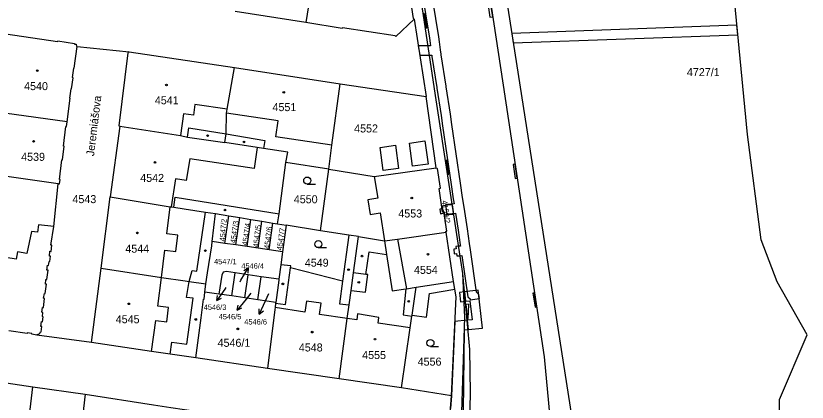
# Model space of a CAD drawing. Extents: x -756746 to -753363, y -1166406 to -1161727.
# Drawn here: x -754988.8 to -754820.8, y -1165946.8 to -1165864.8 of the extents above; entities that cross this region are included whole.
import ezdxf

# ---------------------------------------------------------------- set-up
doc = ezdxf.new("R2010")
doc.units = 0
for name, color, linetype in [('Hranice kat_území', 7, 'Continuous'), ('Hranice parcel', 7, 'Continuous'), ('Parcelní čísla', 7, 'Continuous'), ('Pop  PČ popisy', 7, 'Continuous'), ('Vnitřní kresba', 7, 'Continuous'), ('Věcná břemena k části', 7, 'Continuous'), ('Značky budov', 7, 'Continuous'), ('Značky kultur', 7, 'Continuous')]:
    doc.layers.add(name, color=color, linetype=linetype)

msp = doc.modelspace()

# ---------------------------------------------------------------- linework, layer by layer
at = {"layer": 'Hranice kat_území'}
msp.add_lwpolyline([(-754827.13, -1165983.58), (-754826.69, -1165946.26), (-754820.79, -1165932.53), (-754827.17, -1165921.24), (-754830.58, -1165912.37), (-754833.44, -1165889.97), (-754837.95, -1165843.7)], dxfattribs=at)
at = {"layer": 'Hranice parcel'}
for p, q in [((-754927.22, -1165866.24), (-754942.23, -1165863.89)), ((-754904.23, -1165865.47), (-754901.67, -1165881.94)), ((-754975.76, -1165871.3), (-754964.74, -1165872.4)), ((-754964.74, -1165872.4), (-754942.38, -1165875.74)), ((-754942.38, -1165875.74), (-754919.95, -1165879.22)), ((-754919.95, -1165879.22), (-754901.67, -1165881.94)), ((-754899.53, -1165897.07), (-754901.67, -1165881.94)), ((-754966.7, -1165888.2), (-754968.78, -1165903.24)), ((-754922.31, -1165897.32), (-754931.46, -1165895.91)), ((-754924.11, -1165910.4), (-754922.31, -1165897.32)), ((-754970.69, -1165918.35), (-754968.78, -1165903.24)), ((-754947.08, -1165912.68), (-754946.39, -1165906.78)), ((-754946.39, -1165906.78), (-754943.58, -1165907.24)), ((-754944.4, -1165913.09), (-754943.58, -1165907.24)), ((-754943.58, -1165907.24), (-754941.25, -1165907.63)), ((-754942.06, -1165913.43), (-754941.25, -1165907.63)), ((-754941.25, -1165907.63), (-754938.91, -1165908.01)), ((-754939.7, -1165913.77), (-754938.91, -1165908.01)), ((-754938.91, -1165908.01), (-754936.56, -1165908.4)), ((-754937.34, -1165914.11), (-754936.56, -1165908.4)), ((-754936.56, -1165908.4), (-754934.2, -1165908.79)), ((-754934.98, -1165914.46), (-754934.2, -1165908.79)), ((-754934.2, -1165908.79), (-754933.2, -1165908.95)), ((-754933.2, -1165908.95), (-754931.37, -1165909.24)), ((-754931.37, -1165909.24), (-754932.14, -1165914.86)), ((-754924.11, -1165910.4), (-754931.37, -1165909.24)), ((-754918.12, -1165911.32), (-754924.11, -1165910.4)), ((-754895.85, -1165921.16), (-754897.45, -1165910.69)), ((-754944.4, -1165913.09), (-754947.08, -1165912.68)), ((-754916.04, -1165911.63), (-754918.12, -1165911.32)), ((-754916.04, -1165911.63), (-754910.55, -1165912.57)), ((-754942.06, -1165913.43), (-754944.4, -1165913.09)), ((-754939.7, -1165913.77), (-754942.06, -1165913.43)), ((-754937.34, -1165914.11), (-754939.7, -1165913.77)), ((-754934.98, -1165914.46), (-754937.34, -1165914.11)), ((-754932.14, -1165914.86), (-754934.98, -1165914.46)), ((-754932.14, -1165914.86), (-754932.53, -1165917.68)), ((-754932.53, -1165917.68), (-754932.92, -1165920.68)), ((-754972.7, -1165934.17), (-754970.69, -1165918.35)), ((-754942.92, -1165924.26), (-754942.24, -1165919.37)), ((-754939.45, -1165919.8), (-754942.24, -1165919.37)), ((-754940.17, -1165924.66), (-754939.45, -1165919.8)), ((-754936.69, -1165920.2), (-754939.45, -1165919.8)), ((-754937.38, -1165925.07), (-754936.69, -1165920.2)), ((-754932.92, -1165920.68), (-754936.69, -1165920.2)), ((-754948.63, -1165923.42), (-754948.41, -1165921.7)), ((-754903.78, -1165922.39), (-754895.85, -1165921.16)), ((-754945.66, -1165923.85), (-754948.63, -1165923.42)), ((-754942.92, -1165924.26), (-754945.66, -1165923.85)), ((-754940.17, -1165924.66), (-754942.92, -1165924.26)), ((-754937.38, -1165925.07), (-754940.17, -1165924.66)), ((-754933.6, -1165925.62), (-754937.38, -1165925.07)), ((-754984.31, -1165932.57), (-754984.29, -1165932.43)), ((-754972.7, -1165934.17), (-754984.31, -1165932.57)), ((-754826.69, -1165946.26), (-754820.79, -1165932.53)), ((-754935.37, -1165939.67), (-754950.56, -1165937.42)), ((-754920.11, -1165941.86), (-754935.37, -1165939.67)), ((-754906.91, -1165943.78), (-754920.11, -1165941.86)), ((-754987.57, -1165962.84), (-754985.14, -1165943.54)), ((-754985.14, -1165943.54), (-754974.08, -1165945.13)), ((-754896.29, -1165945.45), (-754906.91, -1165943.78)), ((-754827.13, -1165983.58), (-754826.69, -1165946.26))]:
    msp.add_line(p, q, dxfattribs=at)
for points in [[(-754893.87, -1165919.46), (-754899.67, -1165881.69), (-754902.28, -1165864.2), (-754904.91, -1165847.27), (-754914.1, -1165786.01), (-754916.16, -1165772.03), (-754920.31, -1165744.22), (-754925.86, -1165707.53), (-754934.37, -1165652.04), (-754940.69, -1165610.27), (-754945.47, -1165583.65), (-754957.29, -1165524.97), (-754963.86, -1165505.86), (-754970.07, -1165475.28), (-754974.11, -1165441.89), (-754977.86, -1165423.12), (-754982.77, -1165403.72), (-754984.71, -1165394.8), (-754990.28, -1165381.95), (-754996.53, -1165351.07), (-755004.37, -1165309.56), (-755007.34, -1165270.19), (-755010.72, -1165249.36), (-755016.18, -1165250.63)], [(-754986.88, -1165279.38), (-754990.41, -1165279.86), (-754980.99, -1165331.36), (-754966.52, -1165403.04), (-754962.21, -1165426.7), (-754948.35, -1165495.48), (-754937.5, -1165549.21), (-754928.46, -1165594.05), (-754928.31, -1165595.05), (-754927.98, -1165597.22), (-754926.04, -1165609.85), (-754919.91, -1165650.59), (-754911.7, -1165704.69), (-754902.24, -1165767.33), (-754892.9, -1165829.68), (-754885.35, -1165879.53), (-754876.62, -1165937.17), (-754872.47, -1165981.85), (-754871.4, -1165985.78), (-754868.4, -1165989.67), (-754864.36, -1165991.91), (-754859.05, -1165992.04), (-754854.87, -1165991.29)], [(-754923.98, -1165615.89), (-754912.58, -1165682.53), (-754887.89, -1165840.42), (-754864.72, -1165988.62), (-754860.06, -1165990.02), (-754855.25, -1165989.37)], [(-754833.44, -1165889.97), (-754837.95, -1165843.7), (-754842.97, -1165786.69), (-754844.24, -1165752.2), (-754845.04, -1165691.76), (-754839.18, -1165652.65)], [(-754904.23, -1165865.47), (-754904.34, -1165865.36), (-754906.43, -1165851.68), (-754906.27, -1165851.66), (-754907.29, -1165846.39)], [(-754924.25, -1165847.28), (-754925.14, -1165852.98), (-754925.48, -1165855.12), (-754927.22, -1165866.24)], [(-754904.23, -1165865.47), (-754908.11, -1165869.2), (-754908.24, -1165869.07), (-754919.46, -1165867.31), (-754919.48, -1165867.45), (-754927.22, -1165866.24)], [(-754996.6, -1165867.79), (-754996.58, -1165867.59), (-754995.76, -1165867.71), (-754995.79, -1165867.9), (-754993.52, -1165868.25), (-754993.49, -1165868.05), (-754992.86, -1165868.15), (-754992.88, -1165868.3), (-754979.91, -1165870.24), (-754979.89, -1165870.09), (-754976.29, -1165870.64), (-754976.31, -1165870.8), (-754975.99, -1165870.84), (-754975.88, -1165871.28), (-754975.76, -1165871.3)], [(-754977.88, -1165887.32), (-754977.22, -1165882.29), (-754977.35, -1165882.27), (-754977.06, -1165880.26), (-754976.95, -1165880.28), (-754976.64, -1165877.92), (-754976.74, -1165877.91), (-754976.5, -1165875.92), (-754976.38, -1165875.93), (-754975.76, -1165871.3)], [(-754964.74, -1165872.4), (-754965.01, -1165872.63), (-754966.89, -1165888.17), (-754966.7, -1165888.2)], [(-754944.43, -1165891.7), (-754944.11, -1165889.85), (-754944.04, -1165885.45), (-754943.89, -1165884.59), (-754942.38, -1165875.74)], [(-754922.31, -1165897.32), (-754921.72, -1165892.27), (-754919.95, -1165879.22)], [(-754977.88, -1165887.32), (-754991.18, -1165885.43), (-754998.96, -1165884.18)], [(-754979.76, -1165900.42), (-754979.52, -1165900.45), (-754979.4, -1165899.51), (-754979.52, -1165899.5), (-754979, -1165895.33), (-754978.88, -1165895.35), (-754978.53, -1165892.48), (-754978.64, -1165892.46), (-754978.13, -1165888.3), (-754978.01, -1165888.31), (-754977.88, -1165887.32)], [(-754966.7, -1165888.2), (-754953.85, -1165890.21), (-754952.34, -1165890.53), (-754944.43, -1165891.7)], [(-754820.79, -1165932.53), (-754827.17, -1165921.24), (-754830.58, -1165912.37), (-754833.44, -1165889.97)], [(-754931.46, -1165895.91), (-754931.05, -1165893.7), (-754936.19, -1165892.93), (-754937.53, -1165892.73), (-754944.43, -1165891.7)], [(-754933.2, -1165908.95), (-754932.89, -1165906.8), (-754931.46, -1165895.91)], [(-754979.76, -1165900.42), (-754992.77, -1165898.65), (-755000.73, -1165897.43)], [(-754922.31, -1165897.32), (-754912.69, -1165898.87), (-754899.53, -1165897.07)], [(-754897.45, -1165910.69), (-754897.48, -1165910.5), (-754897.27, -1165910.47), (-754897.9, -1165906.33), (-754898.18, -1165906.37), (-754898.92, -1165901.43), (-754898.65, -1165901.39), (-754899.3, -1165897.22), (-754899.5, -1165897.25), (-754899.53, -1165897.07)], [(-754983.53, -1165931.87), (-754983.4, -1165931.88), (-754983.26, -1165930.76), (-754983.48, -1165930.74), (-754983.35, -1165929.71), (-754983.13, -1165929.74), (-754983, -1165928.66), (-754983.15, -1165928.65), (-754983.04, -1165927.75), (-754983.24, -1165927.73), (-754983.11, -1165926.72), (-754982.91, -1165926.74), (-754982.67, -1165924.78), (-754982.88, -1165924.75), (-754982.69, -1165923.73), (-754982.55, -1165923.75), (-754982.3, -1165921.76), (-754982.5, -1165921.74), (-754982.4, -1165920.74), (-754982.18, -1165920.77), (-754981.93, -1165918.78), (-754982.17, -1165918.75), (-754982.05, -1165917.75), (-754981.81, -1165917.78), (-754981.67, -1165916.94), (-754981.55, -1165916.95), (-754981.42, -1165915.84), (-754981.66, -1165915.81), (-754981.53, -1165914.78), (-754981.29, -1165914.81), (-754981.13, -1165913.48), (-754981.35, -1165913.45), (-754980.71, -1165909.49), (-754979.76, -1165900.42)], [(-754968.78, -1165903.24), (-754955.99, -1165905.31), (-754955.83, -1165905.34), (-754955.27, -1165905.43), (-754953.03, -1165905.79), (-754948.55, -1165906.46), (-754946.39, -1165906.78)], [(-754910.55, -1165912.57), (-754907.74, -1165912.17), (-754897.45, -1165910.69)], [(-754948.41, -1165921.7), (-754948.08, -1165919.32), (-754947.19, -1165913.6), (-754947.08, -1165912.68)], [(-754918.12, -1165911.32), (-754919.45, -1165921.09), (-754930.46, -1165918.27), (-754930.41, -1165917.85), (-754932.53, -1165917.68)], [(-754920.11, -1165941.86), (-754918.41, -1165929.05), (-754918.03, -1165926.17), (-754917.61, -1165923.07), (-754917.12, -1165919.34), (-754916.04, -1165911.63)], [(-754910.55, -1165912.57), (-754910.1, -1165915.45), (-754908.89, -1165923.18), (-754906.01, -1165922.74), (-754905.86, -1165922.72), (-754903.78, -1165922.39)], [(-754970.69, -1165918.35), (-754957.84, -1165920.32), (-754952.85, -1165921.08), (-754952.01, -1165921.21), (-754948.41, -1165921.7)], [(-754942.24, -1165919.37), (-754944.04, -1165919.09), (-754944.73, -1165919.23), (-754945.07, -1165919.84), (-754945.66, -1165923.85)], [(-754899.06, -1165997.62), (-754897.71, -1165996.12), (-754896.74, -1165994.68), (-754896.09, -1165993.18), (-754895.65, -1165991.02), (-754895.42, -1165989.19), (-754895.29, -1165985.92), (-754895.17, -1165981), (-754894.31, -1165955.68), (-754893.44, -1165928.76), (-754893.87, -1165919.46)], [(-754893.38, -1165996.51), (-754893.19, -1165986.65), (-754892.29, -1165944.8), (-754892.4, -1165935.64), (-754893.87, -1165919.46)], [(-754932.92, -1165920.68), (-754932.95, -1165920.88), (-754933.6, -1165925.62)], [(-754906.91, -1165943.78), (-754905.07, -1165931), (-754904.7, -1165928.56), (-754904.66, -1165928.31), (-754903.78, -1165922.39)], [(-754896.29, -1165945.45), (-754895.33, -1165924.44), (-754895.59, -1165922.84), (-754895.85, -1165921.16)], [(-754950.56, -1165937.42), (-754949.42, -1165928.88), (-754948.96, -1165924.95), (-754948.83, -1165924.96), (-754948.63, -1165923.42)], [(-754933.6, -1165925.62), (-754933.63, -1165925.82), (-754933.74, -1165926.72), (-754933.79, -1165927.14), (-754935.37, -1165939.67)], [(-754984.31, -1165932.57), (-754985.4, -1165932.4), (-754985.36, -1165932.2), (-754986.35, -1165932.05), (-754986.38, -1165932.25), (-754990.25, -1165931.66)], [(-754984.29, -1165932.43), (-754984.02, -1165932.4), (-754983.83, -1165932.31), (-754983.64, -1165932.12), (-754983.53, -1165931.87)], [(-754950.56, -1165937.42), (-754955.99, -1165936.62), (-754959.95, -1165936.04), (-754972.7, -1165934.17)], [(-755005.55, -1165940.46), (-755000.89, -1165941.34), (-754997.77, -1165941.83), (-754996.1, -1165941.89), (-754985.14, -1165943.54)], [(-754974.08, -1165945.13), (-754974.93, -1165952.42), (-754975.07, -1165953.62), (-754975.38, -1165956.27), (-754975.65, -1165958.56)], [(-754974.08, -1165945.13), (-754959.58, -1165947.35), (-754955.85, -1165947.91), (-754947.14, -1165949.23), (-754944.47, -1165949.64)], [(-754904.83, -1165955.7), (-754897.71, -1165956.76), (-754897.12, -1165957.25), (-754896.9, -1165954.25), (-754896.53, -1165948.14), (-754896.29, -1165945.45)]]:
    msp.add_lwpolyline(points, dxfattribs=at)
at = {"layer": 'Pop  PČ popisy'}
for p, q in [((-754940.99, -1165920.9), (-754939.44, -1165918.33)), ((-754939.44, -1165918.33), (-754940.39, -1165918.93)), ((-754939.44, -1165918.33), (-754939.53, -1165919.44)), ((-754941.19, -1165921.24), (-754940.99, -1165920.9)), ((-754944.4, -1165922.79), (-754946.12, -1165925.25)), ((-754944.18, -1165922.47), (-754944.4, -1165922.79)), ((-754946.12, -1165925.25), (-754945.96, -1165924.14)), ((-754938.88, -1165923.68), (-754939.91, -1165924.94)), ((-754935.17, -1165923.82), (-754935.87, -1165925.35)), ((-754946.12, -1165925.25), (-754945.14, -1165924.72)), ((-754939.91, -1165924.94), (-754941.8, -1165927.27)), ((-754941.8, -1165927.27), (-754941.56, -1165926.18)), ((-754935.87, -1165925.35), (-754937.09, -1165928.09)), ((-754941.8, -1165927.27), (-754940.78, -1165926.81)), ((-754937.09, -1165928.09), (-754937.14, -1165926.97)), ((-754937.09, -1165928.09), (-754936.23, -1165927.38))]:
    msp.add_line(p, q, dxfattribs=at)
at = {"layer": 'Vnitřní kresba'}
for p, q in [((-754950.75, -1165883.63), (-754951.07, -1165885.89)), ((-754943.89, -1165884.59), (-754950.75, -1165883.63)), ((-754953.2, -1165885.59), (-754953.85, -1165890.21)), ((-754951.07, -1165885.89), (-754953.2, -1165885.59)), ((-754933.06, -1165887.11), (-754944.04, -1165885.45)), ((-754933.56, -1165890.46), (-754933.06, -1165887.11)), ((-754952.34, -1165890.53), (-754952.02, -1165888.58)), ((-754952.02, -1165888.58), (-754944.11, -1165889.85)), ((-754944.11, -1165889.85), (-754935.93, -1165891.23)), ((-754921.72, -1165892.27), (-754933.56, -1165890.46)), ((-754935.93, -1165891.23), (-754936.19, -1165892.93)), ((-754911.47, -1165892.72), (-754908.2, -1165892.23)), ((-754908.2, -1165892.23), (-754907.52, -1165897.17)), ((-754905.22, -1165891.79), (-754901.95, -1165891.31)), ((-754904.55, -1165896.73), (-754905.22, -1165891.79)), ((-754901.95, -1165891.31), (-754901.28, -1165896.25)), ((-754937.53, -1165892.73), (-754938.19, -1165897.18)), ((-754910.79, -1165897.65), (-754911.47, -1165892.72)), ((-754951.84, -1165895.15), (-754952.59, -1165899.75)), ((-754938.19, -1165897.18), (-754951.84, -1165895.15)), ((-754907.52, -1165897.17), (-754910.79, -1165897.65)), ((-754901.28, -1165896.25), (-754904.55, -1165896.73)), ((-754912.69, -1165898.87), (-754911.96, -1165903.53)), ((-754954.86, -1165899.38), (-754955.83, -1165905.34)), ((-754952.59, -1165899.75), (-754954.86, -1165899.38)), ((-754955.27, -1165905.43), (-754954.92, -1165903.26)), ((-754954.92, -1165903.26), (-754932.89, -1165906.8)), ((-754911.96, -1165903.53), (-754914.02, -1165903.87)), ((-754914.02, -1165903.87), (-754913.53, -1165906.96)), ((-754956.7, -1165911.06), (-754955.99, -1165905.31)), ((-754950.37, -1165919.01), (-754948.55, -1165906.46)), ((-754913.53, -1165906.96), (-754911.47, -1165906.64)), ((-754911.47, -1165906.64), (-754910.55, -1165912.57)), ((-754983.99, -1165909.15), (-754984.15, -1165910.7)), ((-754980.71, -1165909.49), (-754983.99, -1165909.15)), ((-754985.44, -1165910.56), (-754986.43, -1165915.21)), ((-754984.15, -1165910.7), (-754985.44, -1165910.56)), ((-754954.4, -1165911.35), (-754956.7, -1165911.06)), ((-754954.83, -1165914.8), (-754954.4, -1165911.35)), ((-754907.74, -1165912.17), (-754905.86, -1165922.72)), ((-754988.68, -1165916.43), (-754999.3, -1165914.86)), ((-754988.45, -1165914.91), (-754988.68, -1165916.43)), ((-754986.43, -1165915.21), (-754988.45, -1165914.91)), ((-754957.84, -1165920.32), (-754957.13, -1165914.51)), ((-754957.13, -1165914.51), (-754954.83, -1165914.8)), ((-754914.45, -1165919.7), (-754913.74, -1165914.88)), ((-754913.74, -1165914.88), (-754910.1, -1165915.45)), ((-754952.01, -1165921.21), (-754951.36, -1165918.88)), ((-754951.36, -1165918.88), (-754950.37, -1165919.01)), ((-754931.52, -1165926.1), (-754930.46, -1165918.27)), ((-754914.45, -1165919.7), (-754917.12, -1165919.34)), ((-754958.66, -1165926.41), (-754957.84, -1165920.32)), ((-754919.45, -1165921.09), (-754920.1, -1165925.9)), ((-754914.52, -1165923.47), (-754914.02, -1165919.72)), ((-754914.02, -1165919.72), (-754914.45, -1165919.7)), ((-754952.52, -1165924.56), (-754952.01, -1165921.21)), ((-754906.01, -1165922.74), (-754906.56, -1165928.28)), ((-754917.61, -1165923.07), (-754914.52, -1165923.47)), ((-754901.63, -1165928.77), (-754900.96, -1165923.76)), ((-754900.96, -1165923.76), (-754895.59, -1165922.84)), ((-754951.15, -1165924.71), (-754952.52, -1165924.56)), ((-754952.45, -1165934.51), (-754951.15, -1165924.71)), ((-754933.63, -1165925.82), (-754931.52, -1165926.1)), ((-754927.06, -1165925.38), (-754927.4, -1165927.68)), ((-754923.93, -1165925.82), (-754927.06, -1165925.38)), ((-754924.28, -1165928.16), (-754923.93, -1165925.82)), ((-754920.1, -1165925.9), (-754918.03, -1165926.17)), ((-754956.35, -1165926.72), (-754958.66, -1165926.41)), ((-754956.75, -1165929.78), (-754956.35, -1165926.72)), ((-754927.4, -1165927.68), (-754933.74, -1165926.72)), ((-754959.95, -1165936.04), (-754959.07, -1165929.47)), ((-754959.07, -1165929.47), (-754956.75, -1165929.78)), ((-754918.41, -1165929.05), (-754924.28, -1165928.16)), ((-754916.41, -1165929.34), (-754918.41, -1165929.05)), ((-754916.22, -1165928.08), (-754916.41, -1165929.34)), ((-754911.71, -1165928.81), (-754916.22, -1165928.08)), ((-754911.89, -1165930), (-754911.71, -1165928.81)), ((-754906.56, -1165928.28), (-754904.7, -1165928.56)), ((-754904.66, -1165928.31), (-754901.63, -1165928.77)), ((-754905.07, -1165931), (-754911.89, -1165930)), ((-754955.99, -1165936.62), (-754955.63, -1165934.1)), ((-754955.63, -1165934.1), (-754952.45, -1165934.51))]:
    msp.add_line(p, q, dxfattribs=at)
at = {"layer": 'Věcná břemena k části'}
for points in [[(-754903.55, -1165853.51), (-754900.99, -1165869.56), (-754900.82, -1165870.58), (-754900.75, -1165871.17), (-754901.24, -1165871.17), (-754903.34, -1165871.17), (-754903.03, -1165873.17), (-754900.94, -1165873.17), (-754900.5, -1165873.17), (-754900.45, -1165873.43), (-754899.4, -1165880.02), (-754899.38, -1165880.16), (-754898.48, -1165885.98), (-754898.18, -1165888.14), (-754896.34, -1165900.59), (-754895.93, -1165903.66), (-754895.76, -1165904.71), (-754896.13, -1165904.75), (-754896.43, -1165904.79), (-754897.55, -1165904.93), (-754897.31, -1165906.91), (-754896.17, -1165906.77), (-754895.83, -1165906.73), (-754895.44, -1165906.68), (-754894.86, -1165910.32), (-754894.43, -1165913.42)], [(-754890.36, -1165924.83), (-754890.46, -1165923.93), (-754890.96, -1165923.46), (-754892.25, -1165914.44), (-754892.45, -1165913.14), (-754892.88, -1165910.02), (-754893.61, -1165905.44), (-754893.95, -1165903.36), (-754894.36, -1165900.31), (-754896.2, -1165887.86), (-754896.5, -1165885.68), (-754897.4, -1165879.88), (-754897.42, -1165879.72), (-754898.49, -1165873.07), (-754898.51, -1165872.93), (-754898.64, -1165872.04), (-754898.84, -1165870.3), (-754899.01, -1165869.24), (-754901.57, -1165853.17)], [(-754894.43, -1165913.42), (-754894.39, -1165913.69), (-754894.75, -1165913.72), (-754895.34, -1165913.76), (-754895.3, -1165914.26), (-754895.8, -1165914.3), (-754895.72, -1165915.3), (-754895.22, -1165915.26), (-754895.18, -1165915.76), (-754894.45, -1165915.71), (-754894.1, -1165915.68), (-754892.84, -1165924.44), (-754892.36, -1165924.89), (-754892.34, -1165925.05), (-754890.36, -1165924.83)], [(-754893.73, -1165948.73), (-754893.52, -1165931.48), (-754892.79, -1165931.41), (-754892.97, -1165929.42), (-754895.57, -1165929.67), (-754896.29, -1165945.45), (-754896.53, -1165948.14)]]:
    msp.add_lwpolyline(points, dxfattribs=at)
for points in [[(-754888.57, -1165862.11), (-754888.17, -1165865.09), (-754887.55, -1165865.01), (-754888, -1165862.03)], [(-754902.25, -1165864.39), (-754901.81, -1165867.37), (-754901.56, -1165867.33), (-754902.06, -1165864.36)], [(-754883.18, -1165870.52), (-754835.5, -1165868.79), (-754835.7, -1165866.8), (-754883.5, -1165868.53)], [(-754897.55, -1165895.48), (-754897.09, -1165898.46), (-754896.87, -1165898.43), (-754897.31, -1165895.44)], [(-754883.23, -1165896.35), (-754882.8, -1165899.32), (-754882.36, -1165899.26), (-754882.81, -1165896.29)], [(-754897.85, -1165906.64), (-754897.9, -1165906.33), (-754898.18, -1165906.37), (-754898.28, -1165905.71), (-754898.77, -1165905.82), (-754898.6, -1165906.81)], [(-754897.85, -1165906.64), (-754897.78, -1165907.14), (-754896.71, -1165906.89), (-754895.8, -1165906.88), (-754896.11, -1165904.89), (-754896.95, -1165904.89), (-754898.35, -1165905.22), (-754898.28, -1165905.71), (-754898.18, -1165906.37), (-754897.9, -1165906.33)], [(-754893.33, -1165925.38), (-754893.51, -1165923.39), (-754894.6, -1165923.52), (-754894.36, -1165925.51)], [(-754892.79, -1165931.41), (-754889.69, -1165931.12), (-754890.65, -1165923.05), (-754893.51, -1165923.39), (-754893.33, -1165925.38), (-754892.4, -1165925.27), (-754891.91, -1165929.32), (-754892.97, -1165929.42)], [(-754879.03, -1165923.65), (-754878.51, -1165926.62), (-754878.23, -1165926.57), (-754878.68, -1165923.59)], [(-754893.28, -1165926.01), (-754893, -1165929.04), (-754892.79, -1165929.05), (-754892.61, -1165926.04)]]:
    msp.add_lwpolyline(points, close=True, dxfattribs=at)
at = {"layer": 'Značky budov'}
for centre in [(-754984.22, -1165876.43), (-754956.81, -1165879.47), (-754931.89, -1165881.02), (-754948.07, -1165890.22), (-754985.01, -1165891.45), (-754940.35, -1165891.56), (-754959.22, -1165895.91), (-754904.73, -1165903.47), (-754944.38, -1165906.02), (-754962.97, -1165910.87), (-754948.55, -1165914.63), (-754915.29, -1165915.8), (-754901.29, -1165915.4), (-754918.15, -1165918.66), (-754932.09, -1165921.69), (-754915.97, -1165921.35), (-754964.8, -1165925.93), (-754905.38, -1165925.39), (-754950.57, -1165929.25), (-754941.66, -1165931.25), (-754925.87, -1165931.93), (-754912.55, -1165933.43)]:
    msp.add_circle(centre, 0.175, dxfattribs=at)
at = {"layer": 'Značky kultur'}
for p, q in [((-754926.92, -1165900.51), (-754925.17, -1165900.51)), ((-754924.57, -1165914), (-754922.82, -1165914)), ((-754900.77, -1165935), (-754899.02, -1165935))]:
    msp.add_line(p, q, dxfattribs=at)
for centre in [(-754926.92, -1165899.76), (-754924.57, -1165913.25), (-754900.77, -1165934.25)]:
    msp.add_circle(centre, 0.75, dxfattribs=at)

# ---------------------------------------------------------------- texts
at = {"layer": 'Parcelní čísla'}
for s, height, p in [('4727/1', 1.7, (-754846.32, -1165877.59)), ('4540', 1.7, (-754987.02, -1165880.56)), ('4541', 1.7, (-754959.27, -1165883.57)), ('4551', 1.7, (-754934.29, -1165885.02)), ('4552', 1.7, (-754916.96, -1165889.55)), ('4539', 1.7, (-754987.65, -1165895.57)), ('4542', 1.7, (-754962.37, -1165900.05)), ('4543', 1.7, (-754976.76, -1165904.55)), ('4550', 1.7, (-754929.77, -1165904.58)), ('4553', 1.7, (-754907.58, -1165907.6)), ('4544', 1.7, (-754965.53, -1165915.07)), ('4547/1', 1.139, (-754946.7, -1165917.52)), ('4546/4', 1.139, (-754940.91, -1165918.46)), ('4549', 1.7, (-754927.43, -1165918.04)), ('4554', 1.7, (-754904.26, -1165919.57)), ('4546/3', 1.139, (-754948.9, -1165927.22)), ('4545', 1.7, (-754967.57, -1165930.05)), ('4546/5', 1.139, (-754945.72, -1165929.22)), ('4546/6', 1.139, (-754940.28, -1165930.32)), ('4546/1', 1.7, (-754945.95, -1165935.05)), ('4548', 1.7, (-754928.7, -1165936.04)), ('4555', 1.7, (-754915.26, -1165937.65)), ('4556', 1.7, (-754903.48, -1165939.05))]:
    msp.add_text(s, height=height, dxfattribs=at).set_placement(p)
for s, height, rotation, p in [('4159/2', 1.2, 278, (-754898.4, -1165904.05)), ('4547/2', 1.139, 85, (-754944.42, -1165912.72)), ('4547/3', 1.139, 82, (-754942.14, -1165913.14)), ('4547/4', 1.139, 82, (-754939.64, -1165913.63)), ('4547/5', 1.139, 83, (-754937.31, -1165914.02)), ('4547/6', 1.139, 83, (-754934.96, -1165914.34)), ('4547/7', 1.139, 82, (-754932.28, -1165914.64))]:
    msp.add_text(s, height=height, rotation=rotation, dxfattribs=at).set_placement(p)
at = {"layer": 'Pop  PČ popisy'}
msp.add_text('Jeremiášova', height=1.7, rotation=83, dxfattribs=at).set_placement((-754972.18, -1165894.63))

doc.saveas('drawing.dxf')
